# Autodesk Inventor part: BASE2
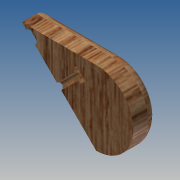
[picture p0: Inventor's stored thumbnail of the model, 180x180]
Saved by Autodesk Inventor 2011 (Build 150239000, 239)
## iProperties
Created: 2011-01
Part Number: BASE2
Document SubType Name: Modeling
Designer: Microsoft
Density: 1 g/cm^3
Author: Microsoft
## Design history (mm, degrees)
sketch "Sketch1"
  geometry: L1 (9.525, 0)-(9.525, 19.05); L2 (-9.525, 19.05)-(-9.525, 0); L3 (-9.525, 19.05)-(9.525, 0); A1 r 9.525 centre (0, 0) between (-9.525, 0) and (9.525, 0); A2 r 9.525 centre (0, 19.05) between (9.525, 19.05) and (-9.525, 19.05); 1 further point
  constraints: 6 end point, 4 point on circle, 3 tangent, 2 centre point, 1 coincident, 1 vertical alignment
  dimensions: "d3" = 9.525 radius of A2; "d4" = 9.525 radius of A1; "d5" = 19.05 distance of L1.start L1.end; "d6" = 19.05 distance of point (0, 0) A2.centre
extrude "Extrusion1" new body sketch "Sketch1" distance "d7" = 12.7; taper "d8" = 0 deg
sketch "Sketch2"
  geometry: L1 (13.47, 0)-(13.47, 12.7) reference; L2 (0, 0)-(26.941, 0) reference; C1 r 0.794 at (13.47, 6.35); 1 further point
  constraints: 1 centre point, 1 midpoint
  dimensions: "d31" = 1.5875 diameter of C1; "d32" = 6.35 distance from line of L2 C1.centre
extrude "Extrusion2" cut sketch "Sketch2" distance "d10" = 6.35; taper "d11" = 0 deg
sketch "Sketch3"
  geometry: C1 r 1.587 at (0, -3.175); C2 r 0.794 at (0, -3.175) reference; 1 further point
  constraints: 1 centre point, 1 concentric
  dimensions: "d12" = 3.175 diameter of C1
extrude "Extrusion3" cut sketch "Sketch3" distance "d13" = 1.5875; taper "d14" = 0 deg
workplane "Work Plane1"
sketch "Sketch5"
  geometry: L1 (-9.525, 19.05)-(-8.622, 19.953); L2 (9.525, 0)-(-9.525, 19.05) reference; C1 r 0.794 at (-7.28, 16.805); 1 further point
  constraints: 2 end point, 1 centre point, 1 perpendicular, 1 point on line
  dimensions: "d21" = 1.5875 diameter of C1; "d22" = 3.175 distance from line of L1 C1.centre
extrude "Extrusion4" cut sketch "Sketch5" distance "d23" = 3.175; taper "d24" = 0 deg
sketch "Sketch6"
  geometry: C1 r 1.588 at (-7.28, -16.805); A1 r 0.794 centre (-7.28, -16.805) between (-6.719, -16.244) and (-7.841, -17.366) reference; 1 further point
  constraints: 1 centre point, 1 coincident
  dimensions: "d25" = 3.175 diameter of C1
extrude "Extrusion5" cut sketch "Sketch6" distance "d26" = 1.5875; taper "d27" = 0 deg
fillet "Fillet1" dims "d30" = 2.54
sketch "Sketch8"
  geometry: L1 (-9.525, 19.05)-(9.525, 0) reference; L2 (-9.525, 0)-(-9.525, 19.05) reference; A1 r 9.525 centre (0, 0) between (-9.525, 0) and (9.525, 0) reference
extrude "Extrusion7" cut sketch "Sketch8" distance "d33" = 3.175; taper "d34" = 0 deg
sketch "Sketch9"
  geometry: L1 (7.841, -17.366)-(6.719, -16.244) reference; C1 r 1.588 at (7.28, -16.805); A1 r 0.794 centre (7.28, -16.805) between (6.719, -16.244) and (7.841, -17.366) reference; 1 further point
  constraints: 1 centre point, 1 coincident
  dimensions: "d37" = 3.175 diameter of C1
extrude "Extrusion8" cut sketch "Sketch9" distance "d35" = 0.79375; taper "d36" = 0 deg
sketch "Sketch10"
  geometry: L1 (-6.719, 16.244)-(9.525, 0) reference; L2 (-9.525, 19.05)-(-7.841, 17.366) reference; L3 (-9.525, 0)-(-9.525, 19.05) reference; A1 r 0.794 centre (-7.28, 16.805) between (-7.841, 17.366) and (-6.719, 16.244) reference; A2 r 9.525 centre (0, 0) between (-9.525, 0) and (9.525, 0) reference
extrude "Extrusion9" cut sketch "Sketch10" distance "d38" = 3.175; taper "d39" = 0 deg
mirror "Mirror1"
body "Solid1"
other parameters: "d17" = -6.35
